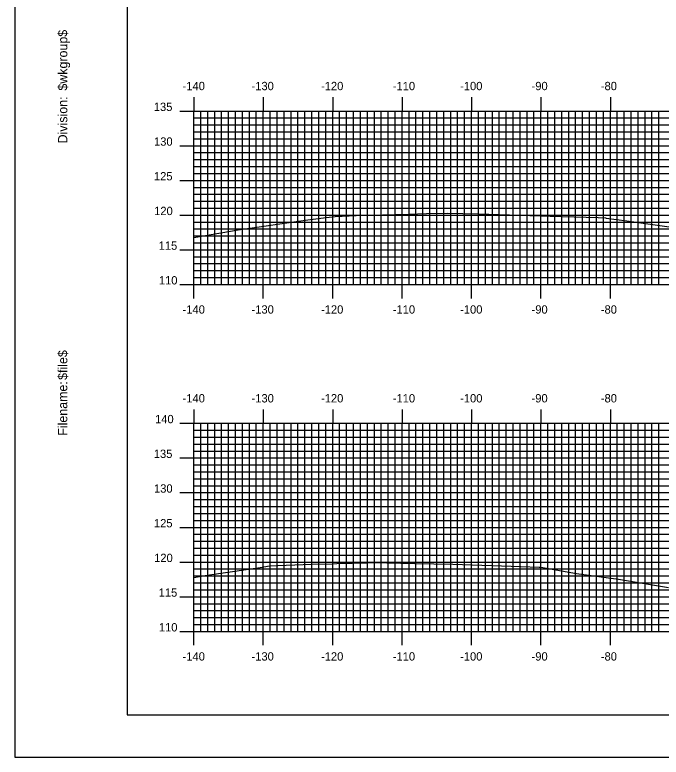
# Model space of a CAD drawing. Extents: x 852540 to 852884, y 364661 to 364881.
# Drawn here: x 852540.5 to 852633.6, y 364661.3 to 364768.2 of the extents above; entities that cross this region are included whole.
import ezdxf

# ---------------------------------------------------------------- set-up
doc = ezdxf.new("R2010")
doc.units = 0
for name, color, linetype in [('BORDER', 7, 'Continuous'), ('H_V ANNOTATION', 7, 'Continuous'), ('M_Roadway_Centerline', 7, 'Continuous'), ('MAJOR', 7, 'Continuous'), ('MINOR', 7, 'Continuous'), ('PLOT BOUNDARY', 7, 'Continuous'), ('S_Roadway_Centerline', 7, 'Continuous')]:
    doc.layers.add(name, color=color, linetype=linetype)

msp = doc.modelspace()

# ---------------------------------------------------------------- linework, layer by layer
at = {"layer": 'BORDER'}
msp.add_lwpolyline([(852556.67, 364667.37), (852876.67, 364667.37), (852876.67, 364877.37), (852556.67, 364877.37)], close=True, dxfattribs=at)
at = {"layer": 'MAJOR'}
for p, q in [((852566.27, 364756.37), (852566.27, 364754.37)), ((852576.27, 364756.37), (852576.27, 364754.37)), ((852586.27, 364756.37), (852586.27, 364754.37)), ((852596.27, 364756.37), (852596.27, 364754.37)), ((852606.27, 364756.37), (852606.27, 364754.37)), ((852616.27, 364756.37), (852616.27, 364754.37)), ((852626.27, 364756.37), (852626.27, 364754.37)), ((852564.26, 364754.37), (852566.27, 364754.37)), ((852566.27, 364754.37), (852846.27, 364754.37)), ((852566.27, 364729.37), (852566.27, 364754.37)), ((852566.27, 364729.37), (852566.27, 364754.37)), ((852566.27, 364754.37), (852846.27, 364754.37)), ((852576.27, 364729.37), (852576.27, 364754.37)), ((852586.27, 364729.37), (852586.27, 364754.37)), ((852596.27, 364729.37), (852596.27, 364754.37)), ((852606.27, 364729.37), (852606.27, 364754.37)), ((852616.27, 364729.37), (852616.27, 364754.37)), ((852626.27, 364729.37), (852626.27, 364754.37)), ((852564.26, 364749.37), (852566.27, 364749.37)), ((852566.27, 364749.37), (852846.27, 364749.37)), ((852564.26, 364744.37), (852566.27, 364744.37)), ((852566.27, 364744.37), (852846.27, 364744.37)), ((852564.26, 364739.37), (852566.27, 364739.37)), ((852566.27, 364739.37), (852846.27, 364739.37)), ((852564.26, 364734.37), (852566.27, 364734.37)), ((852566.27, 364734.37), (852846.27, 364734.37)), ((852564.26, 364729.37), (852566.27, 364729.37)), ((852566.27, 364729.37), (852846.27, 364729.37)), ((852566.27, 364729.37), (852846.27, 364729.37)), ((852566.27, 364727.37), (852566.27, 364729.37)), ((852576.27, 364727.37), (852576.27, 364729.37)), ((852586.27, 364727.37), (852586.27, 364729.37)), ((852596.27, 364727.37), (852596.27, 364729.37)), ((852606.27, 364727.37), (852606.27, 364729.37)), ((852616.27, 364727.37), (852616.27, 364729.37)), ((852626.27, 364727.37), (852626.27, 364729.37)), ((852566.27, 364711.37), (852566.27, 364709.37)), ((852576.27, 364711.37), (852576.27, 364709.37)), ((852586.27, 364711.37), (852586.27, 364709.37)), ((852596.27, 364711.37), (852596.27, 364709.37)), ((852606.27, 364711.37), (852606.27, 364709.37)), ((852616.27, 364711.37), (852616.27, 364709.37)), ((852626.27, 364711.37), (852626.27, 364709.37)), ((852564.26, 364709.37), (852566.27, 364709.37)), ((852566.27, 364709.37), (852846.27, 364709.37)), ((852566.27, 364679.37), (852566.27, 364709.37)), ((852566.27, 364679.37), (852566.27, 364709.37)), ((852566.27, 364709.37), (852846.27, 364709.37)), ((852576.27, 364679.37), (852576.27, 364709.37)), ((852586.27, 364679.37), (852586.27, 364709.37)), ((852596.27, 364679.37), (852596.27, 364709.37)), ((852606.27, 364679.37), (852606.27, 364709.37)), ((852616.27, 364679.37), (852616.27, 364709.37)), ((852626.27, 364679.37), (852626.27, 364709.37)), ((852564.26, 364704.37), (852566.27, 364704.37)), ((852566.27, 364704.37), (852846.27, 364704.37)), ((852564.26, 364699.37), (852566.27, 364699.37)), ((852566.27, 364699.37), (852846.27, 364699.37)), ((852564.26, 364694.37), (852566.27, 364694.37)), ((852566.27, 364694.37), (852846.27, 364694.37)), ((852564.26, 364689.37), (852566.27, 364689.37)), ((852566.27, 364689.37), (852846.27, 364689.37)), ((852564.26, 364684.37), (852566.27, 364684.37)), ((852566.27, 364684.37), (852846.27, 364684.37)), ((852564.26, 364679.37), (852566.27, 364679.37)), ((852566.27, 364679.37), (852846.27, 364679.37)), ((852566.27, 364679.37), (852846.27, 364679.37)), ((852566.27, 364677.37), (852566.27, 364679.37)), ((852576.27, 364677.37), (852576.27, 364679.37)), ((852586.27, 364677.37), (852586.27, 364679.37)), ((852596.27, 364677.37), (852596.27, 364679.37)), ((852606.27, 364677.37), (852606.27, 364679.37)), ((852616.27, 364677.37), (852616.27, 364679.37)), ((852626.27, 364677.37), (852626.27, 364679.37))]:
    msp.add_line(p, q, dxfattribs=at)
at = {"layer": 'MINOR'}
for p, q in [((852567.27, 364729.37), (852567.27, 364754.37)), ((852568.27, 364729.37), (852568.27, 364754.37)), ((852569.27, 364729.37), (852569.27, 364754.37)), ((852570.27, 364729.37), (852570.27, 364754.37)), ((852571.27, 364729.37), (852571.27, 364754.37)), ((852572.27, 364729.37), (852572.27, 364754.37)), ((852573.27, 364729.37), (852573.27, 364754.37)), ((852574.27, 364729.37), (852574.27, 364754.37)), ((852575.27, 364729.37), (852575.27, 364754.37)), ((852577.27, 364729.37), (852577.27, 364754.37)), ((852578.27, 364729.37), (852578.27, 364754.37)), ((852579.27, 364729.37), (852579.27, 364754.37)), ((852580.27, 364729.37), (852580.27, 364754.37)), ((852581.27, 364729.37), (852581.27, 364754.37)), ((852582.27, 364729.37), (852582.27, 364754.37)), ((852583.27, 364729.37), (852583.27, 364754.37)), ((852584.27, 364729.37), (852584.27, 364754.37)), ((852585.27, 364729.37), (852585.27, 364754.37)), ((852587.27, 364729.37), (852587.27, 364754.37)), ((852588.27, 364729.37), (852588.27, 364754.37)), ((852589.27, 364729.37), (852589.27, 364754.37)), ((852590.27, 364729.37), (852590.27, 364754.37)), ((852591.27, 364729.37), (852591.27, 364754.37)), ((852592.27, 364729.37), (852592.27, 364754.37)), ((852593.27, 364729.37), (852593.27, 364754.37)), ((852594.27, 364729.37), (852594.27, 364754.37)), ((852595.27, 364729.37), (852595.27, 364754.37)), ((852597.27, 364729.37), (852597.27, 364754.37)), ((852598.27, 364729.37), (852598.27, 364754.37)), ((852599.27, 364729.37), (852599.27, 364754.37)), ((852600.27, 364729.37), (852600.27, 364754.37)), ((852601.27, 364729.37), (852601.27, 364754.37)), ((852602.27, 364729.37), (852602.27, 364754.37)), ((852603.27, 364729.37), (852603.27, 364754.37)), ((852604.27, 364729.37), (852604.27, 364754.37)), ((852605.27, 364729.37), (852605.27, 364754.37)), ((852607.27, 364729.37), (852607.27, 364754.37)), ((852608.27, 364729.37), (852608.27, 364754.37)), ((852609.27, 364729.37), (852609.27, 364754.37)), ((852610.27, 364729.37), (852610.27, 364754.37)), ((852611.27, 364729.37), (852611.27, 364754.37)), ((852612.27, 364729.37), (852612.27, 364754.37)), ((852613.27, 364729.37), (852613.27, 364754.37)), ((852614.27, 364729.37), (852614.27, 364754.37)), ((852615.27, 364729.37), (852615.27, 364754.37)), ((852617.27, 364729.37), (852617.27, 364754.37)), ((852618.27, 364729.37), (852618.27, 364754.37)), ((852619.27, 364729.37), (852619.27, 364754.37)), ((852620.27, 364729.37), (852620.27, 364754.37)), ((852621.27, 364729.37), (852621.27, 364754.37)), ((852622.27, 364729.37), (852622.27, 364754.37)), ((852623.27, 364729.37), (852623.27, 364754.37)), ((852624.27, 364729.37), (852624.27, 364754.37)), ((852625.27, 364729.37), (852625.27, 364754.37)), ((852627.27, 364729.37), (852627.27, 364754.37)), ((852628.27, 364729.37), (852628.27, 364754.37)), ((852629.27, 364729.37), (852629.27, 364754.37)), ((852630.27, 364729.37), (852630.27, 364754.37)), ((852631.27, 364729.37), (852631.27, 364754.37)), ((852632.27, 364729.37), (852632.27, 364754.37)), ((852633.27, 364729.37), (852633.27, 364754.37)), ((852566.27, 364753.37), (852846.27, 364753.37)), ((852566.27, 364753.37), (852568.27, 364753.37)), ((852566.27, 364752.37), (852846.27, 364752.37)), ((852566.27, 364752.37), (852568.27, 364752.37)), ((852566.27, 364751.37), (852846.27, 364751.37)), ((852566.27, 364751.37), (852568.27, 364751.37)), ((852566.27, 364750.37), (852846.27, 364750.37)), ((852566.27, 364750.37), (852568.27, 364750.37)), ((852566.27, 364748.37), (852846.27, 364748.37)), ((852566.27, 364748.37), (852568.27, 364748.37)), ((852566.27, 364747.37), (852846.27, 364747.37)), ((852566.27, 364747.37), (852568.27, 364747.37)), ((852566.27, 364746.37), (852846.27, 364746.37)), ((852566.27, 364746.37), (852568.27, 364746.37)), ((852566.27, 364745.37), (852846.27, 364745.37)), ((852566.27, 364745.37), (852568.27, 364745.37)), ((852566.27, 364743.37), (852846.27, 364743.37)), ((852566.27, 364743.37), (852568.27, 364743.37)), ((852566.27, 364742.37), (852846.27, 364742.37)), ((852566.27, 364742.37), (852568.27, 364742.37)), ((852566.27, 364741.37), (852846.27, 364741.37)), ((852566.27, 364741.37), (852568.27, 364741.37)), ((852566.27, 364740.37), (852846.27, 364740.37)), ((852566.27, 364740.37), (852568.27, 364740.37)), ((852566.27, 364738.37), (852846.27, 364738.37)), ((852566.27, 364738.37), (852568.27, 364738.37)), ((852566.27, 364737.37), (852846.27, 364737.37)), ((852566.27, 364737.37), (852568.27, 364737.37)), ((852566.27, 364736.37), (852846.27, 364736.37)), ((852566.27, 364736.37), (852568.27, 364736.37)), ((852566.27, 364735.37), (852846.27, 364735.37)), ((852566.27, 364735.37), (852568.27, 364735.37)), ((852566.27, 364733.37), (852846.27, 364733.37)), ((852566.27, 364733.37), (852568.27, 364733.37)), ((852566.27, 364732.37), (852846.27, 364732.37)), ((852566.27, 364732.37), (852568.27, 364732.37)), ((852566.27, 364731.37), (852846.27, 364731.37)), ((852566.27, 364731.37), (852568.27, 364731.37)), ((852566.27, 364730.37), (852846.27, 364730.37)), ((852566.27, 364730.37), (852568.27, 364730.37)), ((852566.27, 364708.37), (852846.27, 364708.37)), ((852566.27, 364708.37), (852568.27, 364708.37)), ((852567.27, 364679.37), (852567.27, 364709.37)), ((852568.27, 364679.37), (852568.27, 364709.37)), ((852569.27, 364679.37), (852569.27, 364709.37)), ((852570.27, 364679.37), (852570.27, 364709.37)), ((852571.27, 364679.37), (852571.27, 364709.37)), ((852572.27, 364679.37), (852572.27, 364709.37)), ((852573.27, 364679.37), (852573.27, 364709.37)), ((852574.27, 364679.37), (852574.27, 364709.37)), ((852575.27, 364679.37), (852575.27, 364709.37)), ((852577.27, 364679.37), (852577.27, 364709.37)), ((852578.27, 364679.37), (852578.27, 364709.37)), ((852579.27, 364679.37), (852579.27, 364709.37)), ((852580.27, 364679.37), (852580.27, 364709.37)), ((852581.27, 364679.37), (852581.27, 364709.37)), ((852582.27, 364679.37), (852582.27, 364709.37)), ((852583.27, 364679.37), (852583.27, 364709.37)), ((852584.27, 364679.37), (852584.27, 364709.37)), ((852585.27, 364679.37), (852585.27, 364709.37)), ((852587.27, 364679.37), (852587.27, 364709.37)), ((852588.27, 364679.37), (852588.27, 364709.37)), ((852589.27, 364679.37), (852589.27, 364709.37)), ((852590.27, 364679.37), (852590.27, 364709.37)), ((852591.27, 364679.37), (852591.27, 364709.37)), ((852592.27, 364679.37), (852592.27, 364709.37)), ((852593.27, 364679.37), (852593.27, 364709.37)), ((852594.27, 364679.37), (852594.27, 364709.37)), ((852595.27, 364679.37), (852595.27, 364709.37)), ((852597.27, 364679.37), (852597.27, 364709.37)), ((852598.27, 364679.37), (852598.27, 364709.37)), ((852599.27, 364679.37), (852599.27, 364709.37)), ((852600.27, 364679.37), (852600.27, 364709.37)), ((852601.27, 364679.37), (852601.27, 364709.37)), ((852602.27, 364679.37), (852602.27, 364709.37)), ((852603.27, 364679.37), (852603.27, 364709.37)), ((852604.27, 364679.37), (852604.27, 364709.37)), ((852605.27, 364679.37), (852605.27, 364709.37)), ((852607.27, 364679.37), (852607.27, 364709.37)), ((852608.27, 364679.37), (852608.27, 364709.37)), ((852609.27, 364679.37), (852609.27, 364709.37)), ((852610.27, 364679.37), (852610.27, 364709.37)), ((852611.27, 364679.37), (852611.27, 364709.37)), ((852612.27, 364679.37), (852612.27, 364709.37)), ((852613.27, 364679.37), (852613.27, 364709.37)), ((852614.27, 364679.37), (852614.27, 364709.37)), ((852615.27, 364679.37), (852615.27, 364709.37)), ((852617.27, 364679.37), (852617.27, 364709.37)), ((852618.27, 364679.37), (852618.27, 364709.37)), ((852619.27, 364679.37), (852619.27, 364709.37)), ((852620.27, 364679.37), (852620.27, 364709.37)), ((852621.27, 364679.37), (852621.27, 364709.37)), ((852622.27, 364679.37), (852622.27, 364709.37)), ((852623.27, 364679.37), (852623.27, 364709.37)), ((852624.27, 364679.37), (852624.27, 364709.37)), ((852625.27, 364679.37), (852625.27, 364709.37)), ((852627.27, 364679.37), (852627.27, 364709.37)), ((852628.27, 364679.37), (852628.27, 364709.37)), ((852629.27, 364679.37), (852629.27, 364709.37)), ((852630.27, 364679.37), (852630.27, 364709.37)), ((852631.27, 364679.37), (852631.27, 364709.37)), ((852632.27, 364679.37), (852632.27, 364709.37)), ((852633.27, 364679.37), (852633.27, 364709.37)), ((852566.27, 364707.37), (852846.27, 364707.37)), ((852566.27, 364707.37), (852568.27, 364707.37)), ((852566.27, 364706.37), (852846.27, 364706.37)), ((852566.27, 364706.37), (852568.27, 364706.37)), ((852566.27, 364705.37), (852846.27, 364705.37)), ((852566.27, 364705.37), (852568.27, 364705.37)), ((852566.27, 364703.37), (852846.27, 364703.37)), ((852566.27, 364703.37), (852568.27, 364703.37)), ((852566.27, 364702.37), (852846.27, 364702.37)), ((852566.27, 364702.37), (852568.27, 364702.37)), ((852566.27, 364701.37), (852846.27, 364701.37)), ((852566.27, 364701.37), (852568.27, 364701.37)), ((852566.27, 364700.37), (852846.27, 364700.37)), ((852566.27, 364700.37), (852568.27, 364700.37)), ((852566.27, 364698.37), (852846.27, 364698.37)), ((852566.27, 364698.37), (852568.27, 364698.37)), ((852566.27, 364697.37), (852846.27, 364697.37)), ((852566.27, 364697.37), (852568.27, 364697.37)), ((852566.27, 364696.37), (852846.27, 364696.37)), ((852566.27, 364696.37), (852568.27, 364696.37)), ((852566.27, 364695.37), (852846.27, 364695.37)), ((852566.27, 364695.37), (852568.27, 364695.37)), ((852566.27, 364693.37), (852846.27, 364693.37)), ((852566.27, 364693.37), (852568.27, 364693.37)), ((852566.27, 364692.37), (852846.27, 364692.37)), ((852566.27, 364692.37), (852568.27, 364692.37)), ((852566.27, 364691.37), (852846.27, 364691.37)), ((852566.27, 364691.37), (852568.27, 364691.37)), ((852566.27, 364690.37), (852846.27, 364690.37)), ((852566.27, 364690.37), (852568.27, 364690.37)), ((852566.27, 364688.37), (852846.27, 364688.37)), ((852566.27, 364688.37), (852568.27, 364688.37)), ((852566.27, 364687.37), (852846.27, 364687.37)), ((852566.27, 364687.37), (852568.27, 364687.37)), ((852566.27, 364686.37), (852846.27, 364686.37)), ((852566.27, 364686.37), (852568.27, 364686.37)), ((852566.27, 364685.37), (852846.27, 364685.37)), ((852566.27, 364685.37), (852568.27, 364685.37)), ((852566.27, 364683.37), (852846.27, 364683.37)), ((852566.27, 364683.37), (852568.27, 364683.37)), ((852566.27, 364682.37), (852846.27, 364682.37)), ((852566.27, 364682.37), (852568.27, 364682.37)), ((852566.27, 364681.37), (852846.27, 364681.37)), ((852566.27, 364681.37), (852568.27, 364681.37)), ((852566.27, 364680.37), (852846.27, 364680.37)), ((852566.27, 364680.37), (852568.27, 364680.37))]:
    msp.add_line(p, q, dxfattribs=at)
at = {"layer": 'PLOT BOUNDARY'}
msp.add_lwpolyline([(852540.48, 364661.25), (852880.48, 364661.25), (852880.48, 364881.25), (852540.48, 364881.25)], close=True, dxfattribs=at)
at = {"layer": 'S_Roadway_Centerline'}
for points in [[(852566.27, 364736.15), (852572.63, 364737.25), (852582.71, 364738.68), (852585.31, 364739.02), (852586.61, 364739.19), (852589.66, 364739.31), (852597.2, 364739.51), (852599.78, 364739.59), (852602.74, 364739.65), (852607.27, 364739.54), (852611.75, 364739.4), (852617.58, 364739.22), (852624.52, 364739.01), (852625.58, 364738.96), (852625.69, 364738.94), (852628.65, 364738.56), (852635.1, 364737.63)], [(852566.27, 364687.16), (852568.19, 364687.47), (852574.13, 364688.35), (852575.8, 364688.58), (852577.19, 364688.84), (852583.22, 364689.05), (852586.24, 364689.13), (852586.88, 364689.16), (852593.45, 364689.3), (852594.06, 364689.26), (852598.1, 364689.17), (852603.56, 364689.06), (852613.36, 364688.75), (852616.04, 364688.63), (852616.25, 364688.61), (852621.39, 364687.74), (852627.46, 364686.91), (852634.66, 364685.69)]]:
    msp.add_lwpolyline(points, dxfattribs=at)

# ---------------------------------------------------------------- texts
at = {"layer": 'BORDER'}
for s, p in [('$wkgroup$', (852548.04, 364757.31)), ('Division:', (852548.04, 364749.7)), ('$file$', (852548.04, 364715.62)), ('Filename:', (852548.04, 364707.57))]:
    msp.add_text(s, height=1.339, rotation=90, dxfattribs=at).set_placement(p)
at = {"layer": 'H_V ANNOTATION'}
for s, p in [('-140', (852564.65, 364757.37)), ('-130', (852574.58, 364757.37)), ('-120', (852584.59, 364757.37)), ('-110', (852594.93, 364757.37)), ('-100', (852604.63, 364757.37)), ('-90', (852614.92, 364757.37)), ('-80', (852624.9, 364757.37)), ('135', (852560.5, 364754.37)), ('130', (852560.53, 364749.37)), ('125', (852560.52, 364744.37)), ('120', (852560.55, 364739.37)), ('115', (852561.2, 364734.37)), ('110', (852561.23, 364729.37)), ('-140', (852564.65, 364725.17)), ('-130', (852574.58, 364725.17)), ('-120', (852584.59, 364725.17)), ('-110', (852594.93, 364725.17)), ('-100', (852604.63, 364725.17)), ('-90', (852614.92, 364725.17)), ('-80', (852624.9, 364725.17)), ('-140', (852564.65, 364712.37)), ('-130', (852574.58, 364712.37)), ('-120', (852584.59, 364712.37)), ('-110', (852594.93, 364712.37)), ('-100', (852604.63, 364712.37)), ('-90', (852614.92, 364712.37)), ('-80', (852624.9, 364712.37)), ('140', (852560.68, 364709.37)), ('135', (852560.5, 364704.37)), ('130', (852560.53, 364699.37)), ('125', (852560.52, 364694.37)), ('120', (852560.55, 364689.37)), ('115', (852561.2, 364684.37)), ('110', (852561.23, 364679.37)), ('-140', (852564.65, 364675.17)), ('-130', (852574.58, 364675.17)), ('-120', (852584.59, 364675.17)), ('-110', (852594.93, 364675.17)), ('-100', (852604.63, 364675.17)), ('-90', (852614.92, 364675.17)), ('-80', (852624.9, 364675.17))]:
    msp.add_text(s, height=1.2, dxfattribs=at).set_placement(p)
at = {"layer": 'M_Roadway_Centerline'}
for s, p in [('C', (852602.74, 364739.65)), ('L', (852602.74, 364739.64)), ('C', (852593.45, 364689.3)), ('L', (852593.45, 364689.3))]:
    msp.add_text(s, height=0.0146, dxfattribs=at).set_placement(p)
at = {"layer": 'MAJOR'}
for p in [(852566.26, 364729.37), (852566.26, 364679.37)]:
    msp.add_text('-', height=0.012, dxfattribs=at).set_placement(p)

doc.saveas('drawing.dxf')
